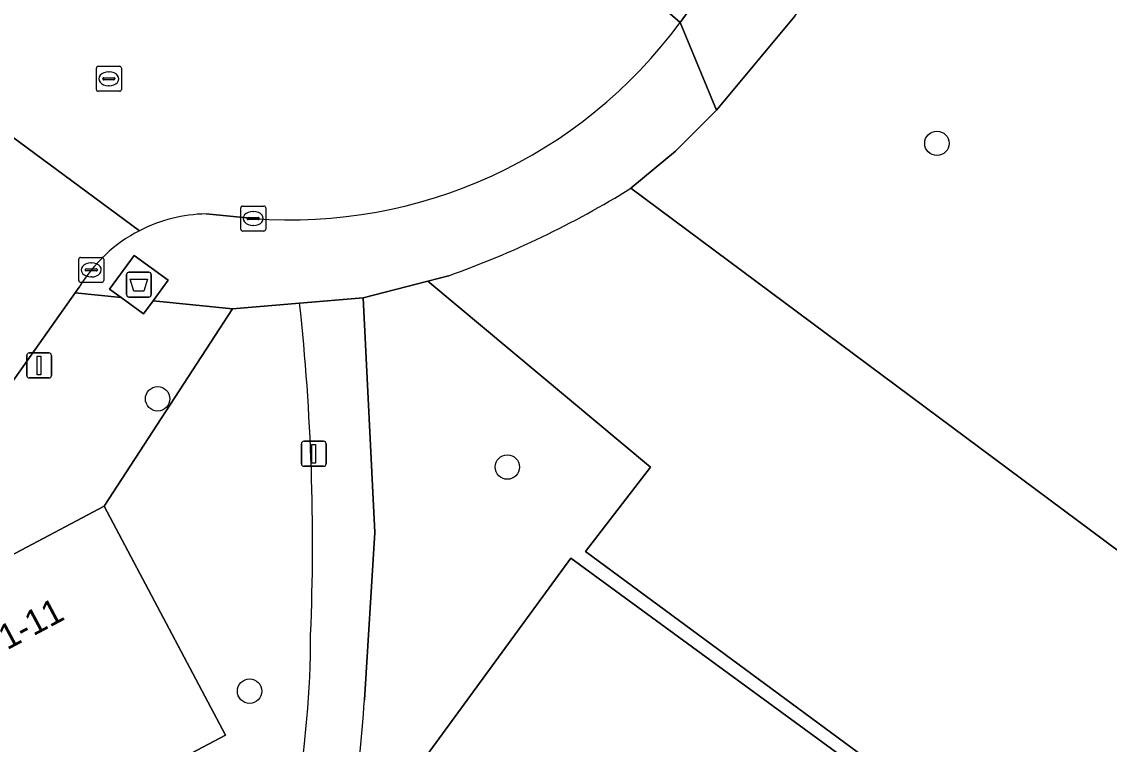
# Model space of a CAD drawing. Extents: x 159674 to 160531, y 382172 to 382904.
# Drawn here: x 160074.9 to 160118.45, y 382301.97 to 382330.89 of the extents above; entities that cross this region are included whole.
import ezdxf

# ---------------------------------------------------------------- set-up
doc = ezdxf.new("R2010")
doc.units = 0
for name, color, linetype in [('IMGEO_Afval_apart_plaats', 7, 'Continuous'), ('IMGEO_Boom', 7, 'Continuous'), ('IMGEO_Erf', 7, 'Continuous'), ('IMGEO_Groenvoorziening', 7, 'Continuous'), ('IMGEO_Kolk', 7, 'Continuous'), ('IMGEO_Lichtmast', 7, 'Continuous'), ('IMGEO_Pand', 7, 'Continuous'), ('IMGEO_Pand_nummerreeks', 7, 'Continuous'), ('IMGEO_Rijbaan_lokaal_gesloten', 7, 'Continuous'), ('IMGEO_Rijbaan_lokaal_open', 7, 'Continuous'), ('IMGEO_Rioolput', 7, 'Continuous'), ('IMGEO_Voetpad_gesloten', 7, 'Continuous'), ('IMGEO_Voetpad_open', 7, 'Continuous')]:
    doc.layers.add(name, color=color, linetype=linetype)

msp = doc.modelspace()

# ---------------------------------------------------------------- linework, layer by layer
at = {"layer": 'IMGEO_Afval_apart_plaats'}
for p, q in [((160079.198, 382320.869), (160079.988, 382320.869)), ((160079.988, 382320.869), (160079.198, 382320.869)), ((160079.098, 382319.969), (160079.098, 382320.769)), ((160079.098, 382320.769), (160079.098, 382319.969)), ((160080.088, 382320.769), (160080.088, 382319.969)), ((160080.088, 382319.969), (160080.088, 382320.769)), ((160079.988, 382319.869), (160079.198, 382319.869)), ((160079.198, 382319.869), (160079.988, 382319.869))]:
    msp.add_line(p, q, dxfattribs=at)
msp.add_lwpolyline([(160079.241, 382320.583), (160079.945, 382320.583), (160079.796, 382320.113), (160079.39, 382320.113), (160079.241, 382320.583)], dxfattribs=at)
for centre, start, end in [((160079.198, 382320.769), 90, 180), ((160079.198, 382320.769), 90, 180), ((160079.988, 382320.769), 0, 90), ((160079.988, 382320.769), 360, 90), ((160079.198, 382319.969), 180, 270), ((160079.198, 382319.969), 180, 270), ((160079.988, 382319.969), 270, 0), ((160079.988, 382319.969), 270, 0)]:
    msp.add_arc(centre, 0.1, start, end, dxfattribs=at)
at = {"layer": 'IMGEO_Boom'}
for centre in [(160111.547, 382326.026), (160080.343, 382315.799), (160094.348, 382313.067), (160084.026, 382304.097)]:
    msp.add_circle(centre, 0.489, dxfattribs=at)
at = {"layer": 'IMGEO_Erf'}
for points in [[(160097.483, 382309.693), (160100.079, 382313.06), (160091.158, 382320.51), (160088.577, 382319.845), (160089.038, 382310.447), (160088.624, 382303.755)], [(160086.028, 382319.631), (160083.339, 382319.397), (160078.204, 382311.499), (160083.057, 382302.331), (160067.532, 382294.112), (160051.977, 382285.878), (160036.422, 382277.643), (160020.867, 382269.409), (160016.014, 382278.577), (160005.765, 382273.145), (160019.447, 382262.957), (160024.762, 382259.009)], [(160094.492, 382291.126), (160137.034, 382260.024), (160146.738, 382273.362), (160097.483, 382309.693)]]:
    msp.add_lwpolyline(points, dxfattribs=at)
msp.add_lwpolyline([(160104.95, 382290.619), (160090.742, 382301.006), (160096.891, 382309.417), (160111.099, 382299.03), (160125.307, 382288.642), (160139.508, 382278.26), (160133.359, 382269.849), (160119.158, 382280.231)], close=True, dxfattribs=at)
for centre, radius, start, end in [((159998.244, 382310.063), 88.304, 357.59334, 6.22037), ((160047.379, 382306.364), 39.091, 340.2477, 359.987), ((160035.838, 382307.132), 52.894, 346.0146, 356.3393)]:
    msp.add_arc(centre, radius, start, end, dxfattribs=at)
at = {"layer": 'IMGEO_Groenvoorziening'}
for points in [[(160105.86, 382331.118), (160102.72, 382327.353), (160101.078, 382325.715), (160099.296, 382324.229), (160154.089, 382283.466)], [(160154.089, 382283.466), (160099.296, 382324.229)], [(160091.998, 382320.726), (160091.158, 382320.51)], [(160091.158, 382320.51), (160100.079, 382313.06), (160097.483, 382309.693), (160146.738, 382273.362)]]:
    msp.add_lwpolyline(points, dxfattribs=at)
msp.add_arc((160079.113, 382356.924), 38.423, 289.5938, 301.6877, dxfattribs=at)
at = {"layer": 'IMGEO_Kolk'}
for p, q in [((160083.749, 382323.516), (160084.601, 382323.516)), ((160083.674, 382322.59), (160083.674, 382323.442)), ((160083.933, 382323.01), (160083.933, 382323.022)), ((160083.976, 382323.059), (160084.374, 382323.059)), ((160084.162, 382323.296), (160084.187, 382323.296)), ((160084.417, 382323.022), (160084.417, 382323.01)), ((160084.675, 382323.442), (160084.675, 382322.59)), ((160084.371, 382322.973), (160083.973, 382322.973)), ((160084.185, 382322.736), (160084.16, 382322.736)), ((160084.601, 382322.516), (160083.749, 382322.516)), ((160077.188, 382320.533), (160077.188, 382321.385)), ((160077.263, 382321.459), (160078.115, 382321.459)), ((160078.189, 382321.385), (160078.189, 382320.533)), ((160077.447, 382320.953), (160077.447, 382320.965)), ((160077.885, 382320.916), (160077.487, 382320.916)), ((160077.49, 382321.002), (160077.888, 382321.002)), ((160077.676, 382321.239), (160077.701, 382321.239)), ((160077.931, 382320.965), (160077.931, 382320.953)), ((160078.115, 382320.459), (160077.263, 382320.459)), ((160077.699, 382320.679), (160077.674, 382320.679))]:
    msp.add_line(p, q, dxfattribs=at)
for points in [[(160083.749, 382323.516), (160084.601, 382323.516)], [(160083.674, 382322.59), (160083.674, 382323.442)], [(160084.675, 382323.442), (160084.675, 382322.59)], [(160084.601, 382322.516), (160083.749, 382322.516)], [(160077.188, 382320.533), (160077.188, 382321.385)], [(160077.263, 382321.459), (160078.115, 382321.459)], [(160078.189, 382321.385), (160078.189, 382320.533)], [(160078.115, 382320.459), (160077.263, 382320.459)]]:
    msp.add_lwpolyline(points, dxfattribs=at)
for centre, radius, start, end in [((160083.751, 382323.44), 0.0765, 91.552, 178.448), ((160083.751, 382323.44), 0.0765, 91.552, 178.448), ((160084.599, 382323.44), 0.0765, 1.552, 88.448), ((160084.599, 382323.44), 0.0765, 1.552, 88.448), ((160083.973, 382323.019), 0.0403, 85.8775, 175.7526), ((160083.97, 382323.009), 0.0366, 178.938, 274.7102), ((160084.374, 382323.016), 0.043, 264.8664, 352.4533), ((160084.378, 382323.021), 0.0386, 1.7309, 96.639), ((160083.751, 382322.592), 0.0765, 181.552, 268.448), ((160083.751, 382322.592), 0.0765, 181.552, 268.448), ((160084.599, 382322.592), 0.0765, 271.552, 358.448), ((160084.599, 382322.592), 0.0765, 271.552, 358.448), ((160077.265, 382321.383), 0.0765, 91.552, 178.448), ((160077.265, 382321.383), 0.0765, 91.552, 178.448), ((160078.113, 382321.383), 0.0765, 1.552, 88.448), ((160078.113, 382321.383), 0.0765, 1.552, 88.448), ((160077.487, 382320.962), 0.0403, 85.8775, 175.7526), ((160077.484, 382320.952), 0.0366, 178.938, 274.7102), ((160077.888, 382320.959), 0.043, 264.8664, 352.4533), ((160077.892, 382320.964), 0.0386, 1.7309, 96.639), ((160077.265, 382320.535), 0.0765, 181.552, 268.448), ((160077.265, 382320.535), 0.0765, 181.552, 268.448), ((160078.113, 382320.535), 0.0765, 271.552, 358.448), ((160078.113, 382320.535), 0.0765, 271.552, 358.448)]:
    msp.add_arc(centre, radius, start, end, dxfattribs=at)
for centre, major_axis, ratio, start_param, end_param in [((160084.161, 382323.016), (-0.387, 0.002), 0.722429, 4.712389, 7.853982), ((160084.186, 382323.016), (-0.39, 0.002), 0.717154, 1.570796, 4.712389), ((160077.675, 382320.959), (-0.387, 0.002), 0.722429, 4.712389, 7.853982), ((160077.7, 382320.959), (-0.39, 0.002), 0.717154, 1.570796, 4.712389)]:
    msp.add_ellipse(centre, major_axis=major_axis, ratio=ratio, start_param=start_param, end_param=end_param, dxfattribs=at)
at = {"layer": 'IMGEO_Lichtmast'}
for p, q in [((160075.103, 382316.733), (160075.103, 382317.533)), ((160075.103, 382317.533), (160075.103, 382316.733)), ((160075.203, 382317.633), (160075.993, 382317.633)), ((160075.993, 382317.633), (160075.203, 382317.633)), ((160076.093, 382317.533), (160076.093, 382316.733)), ((160076.093, 382316.733), (160076.093, 382317.533)), ((160075.993, 382316.633), (160075.203, 382316.633)), ((160075.203, 382316.633), (160075.993, 382316.633)), ((160086.102, 382313.199), (160086.102, 382313.999)), ((160086.102, 382313.999), (160086.102, 382313.199)), ((160086.202, 382314.099), (160086.992, 382314.099)), ((160086.992, 382314.099), (160086.202, 382314.099)), ((160087.092, 382313.999), (160087.092, 382313.199)), ((160087.092, 382313.199), (160087.092, 382313.999)), ((160086.992, 382313.099), (160086.202, 382313.099)), ((160086.202, 382313.099), (160086.992, 382313.099))]:
    msp.add_line(p, q, dxfattribs=at)
for points in [[(160075.523, 382317.508), (160075.673, 382317.508), (160075.673, 382316.758), (160075.523, 382316.758), (160075.523, 382317.508)], [(160086.522, 382313.974), (160086.672, 382313.974), (160086.672, 382313.224), (160086.522, 382313.224), (160086.522, 382313.974)]]:
    msp.add_lwpolyline(points, dxfattribs=at)
for centre, start, end in [((160075.203, 382317.533), 90, 180), ((160075.203, 382317.533), 90, 180), ((160075.993, 382317.533), 0, 90), ((160075.993, 382317.533), 360, 90), ((160075.203, 382316.733), 180, 270), ((160075.203, 382316.733), 180, 270), ((160075.993, 382316.733), 270, 0), ((160075.993, 382316.733), 270, 0), ((160086.202, 382313.999), 90, 180), ((160086.202, 382313.999), 90, 180), ((160086.992, 382313.999), 0, 90), ((160086.992, 382313.999), 360, 90), ((160086.202, 382313.199), 180, 270), ((160086.202, 382313.199), 180, 270), ((160086.992, 382313.199), 270, 0), ((160086.992, 382313.199), 270, 0)]:
    msp.add_arc(centre, 0.1, start, end, dxfattribs=at)
at = {"layer": 'IMGEO_Pand'}
for points in [[(160062.679, 382303.28), (160067.532, 382294.112), (160083.057, 382302.331), (160078.204, 382311.499)], [(160104.95, 382290.619), (160111.099, 382299.03), (160096.891, 382309.417), (160090.742, 382301.006)]]:
    msp.add_lwpolyline(points, close=True, dxfattribs=at)
at = {"layer": 'IMGEO_Rijbaan_lokaal_gesloten'}
for points in [[(160179.328, 382451.773), (160168.227, 382436.541), (160167.872, 382436.054), (160131.527, 382386.158), (160131.264, 382385.796), (160120.578, 382371.104), (160120.218, 382370.61), (160117.262, 382366.539), (160095.963, 382337.199), (160095.222, 382336.136), (160101.268, 382330.867), (160134.37, 382376.353), (160143.85, 382389.399), (160143.915, 382389.491), (160166.91, 382421.18), (160176.58, 382434.549), (160182.656, 382442.82)], [(159969.32, 382402.798), (159992.637, 382385.919), (159992.936, 382385.697), (160000, 382380.567), (160006.662, 382375.729), (160031.337, 382357.71), (160031.812, 382357.364), (160045.029, 382347.737), (160045.468, 382347.417), (160070.304, 382329.392), (160079.622, 382322.53)], [(160101.268, 382330.867), (160095.222, 382336.136)], [(160082.29, 382323.201), (160084.179, 382323.017)]]:
    msp.add_lwpolyline(points, dxfattribs=at)
for centre, radius, start, end in [((160085.647, 382342.347), 19.386, 265.6572, 323.6871), ((160082.394, 382317.149), 6.053, 90.9811, 117.253)]:
    msp.add_arc(centre, radius, start, end, dxfattribs=at)
at = {"layer": 'IMGEO_Rijbaan_lokaal_open'}
for points in [[(160079.622, 382322.53), (160070.304, 382329.392)], [(160073.671, 382315.279), (160077.045, 382320.041), (160077.204, 382320.266)]]:
    msp.add_lwpolyline(points, dxfattribs=at)
msp.add_arc((160082.399, 382317.141), 6.062, 117.2616, 148.9706, dxfattribs=at)
at = {"layer": 'IMGEO_Rioolput'}
for p, q in [((160077.966, 382329.109), (160078.818, 382329.109)), ((160077.891, 382328.183), (160077.891, 382329.035)), ((160078.379, 382328.889), (160078.404, 382328.889)), ((160078.892, 382329.035), (160078.892, 382328.183)), ((160078.15, 382328.603), (160078.15, 382328.615)), ((160078.588, 382328.566), (160078.19, 382328.566)), ((160078.193, 382328.652), (160078.591, 382328.652)), ((160078.402, 382328.329), (160078.377, 382328.329)), ((160078.634, 382328.615), (160078.634, 382328.603)), ((160078.818, 382328.109), (160077.966, 382328.109))]:
    msp.add_line(p, q, dxfattribs=at)
for points in [[(160077.966, 382329.109), (160078.818, 382329.109)], [(160077.891, 382328.183), (160077.891, 382329.035)], [(160078.892, 382329.035), (160078.892, 382328.183)], [(160078.818, 382328.109), (160077.966, 382328.109)]]:
    msp.add_lwpolyline(points, dxfattribs=at)
for centre, radius, start, end in [((160077.968, 382329.033), 0.0765, 91.552, 178.448), ((160077.968, 382329.033), 0.0765, 91.552, 178.448), ((160078.816, 382329.033), 0.0765, 1.552, 88.448), ((160078.816, 382329.033), 0.0765, 1.552, 88.448), ((160078.19, 382328.612), 0.0403, 85.8775, 175.7526), ((160078.187, 382328.602), 0.0366, 178.938, 274.7102), ((160078.591, 382328.609), 0.043, 264.8664, 352.4533), ((160078.595, 382328.614), 0.0386, 1.7309, 96.639), ((160077.968, 382328.185), 0.0765, 181.552, 268.448), ((160077.968, 382328.185), 0.0765, 181.552, 268.448), ((160078.816, 382328.185), 0.0765, 271.552, 358.448), ((160078.816, 382328.185), 0.0765, 271.552, 358.448)]:
    msp.add_arc(centre, radius, start, end, dxfattribs=at)
for centre, major_axis, ratio, start_param, end_param in [((160078.378, 382328.609), (-0.387, 0.002), 0.722429, 4.712389, 7.853982), ((160078.403, 382328.609), (-0.39, 0.002), 0.717154, 1.570796, 4.712389)]:
    msp.add_ellipse(centre, major_axis=major_axis, ratio=ratio, start_param=start_param, end_param=end_param, dxfattribs=at)
at = {"layer": 'IMGEO_Voetpad_gesloten'}
msp.add_lwpolyline([(160080.762, 382320.55), (160079.406, 382321.537), (160078.424, 382320.188), (160078.885, 382319.853), (160079.78, 382319.201), (160080.16, 382319.722)], close=True, dxfattribs=at)
at = {"layer": 'IMGEO_Voetpad_open'}
for points in [[(160134.37, 382376.353), (160101.268, 382330.867), (160102.72, 382327.353), (160105.86, 382331.118), (160112.692, 382340.508)], [(160099.296, 382324.229), (160101.078, 382325.715), (160102.72, 382327.353), (160101.268, 382330.867)], [(160084.179, 382323.017), (160082.29, 382323.201)], [(160077.204, 382320.266), (160077.045, 382320.041), (160078.885, 382319.853), (160078.424, 382320.188), (160079.406, 382321.537), (160080.762, 382320.55), (160080.16, 382319.722), (160083.339, 382319.397), (160086.028, 382319.631), (160088.577, 382319.845), (160091.158, 382320.51), (160091.998, 382320.726)], [(160062.679, 382303.28), (160078.204, 382311.499), (160083.339, 382319.397), (160080.16, 382319.722), (160079.78, 382319.201), (160078.885, 382319.853), (160077.045, 382320.041), (160073.671, 382315.279)], [(160088.624, 382303.755), (160089.038, 382310.447), (160088.577, 382319.845), (160086.028, 382319.631)]]:
    msp.add_lwpolyline(points, dxfattribs=at)
for centre, radius, start, end in [((160085.647, 382342.347), 19.386, 265.6572, 323.6871), ((160079.113, 382356.924), 38.423, 289.5938, 301.6877), ((160082.394, 382317.149), 6.053, 90.9811, 117.253), ((160082.399, 382317.141), 6.062, 117.2616, 148.9706), ((159998.244, 382310.063), 88.304, 357.59334, 6.22037), ((160047.379, 382306.364), 39.091, 340.2477, 359.987), ((160035.838, 382307.132), 52.894, 346.0146, 356.3393)]:
    msp.add_arc(centre, radius, start, end, dxfattribs=at)

# ---------------------------------------------------------------- texts
at = {"layer": 'IMGEO_Pand_nummerreeks'}
msp.add_text('1-11', height=1, rotation=28.1313, dxfattribs=at).set_placement((160074.318, 382305.727))

doc.saveas('drawing.dxf')
